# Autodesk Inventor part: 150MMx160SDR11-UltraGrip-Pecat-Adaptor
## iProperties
Created: 2012-05
Part Number: 150MMx160SDR11-UltraGrip-Pecat-Adaptor
Document SubType Name: Modeling
Designer: D Cole
Density: 1 g/cm^3
Author: D Cole
